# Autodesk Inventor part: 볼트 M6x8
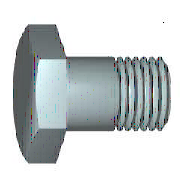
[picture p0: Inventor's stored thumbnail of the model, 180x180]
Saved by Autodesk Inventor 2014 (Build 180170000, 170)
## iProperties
Created: 2012-02
Part Number: 볼트 M6x8
Material: 강철, 연강
Description: 6각 머리 볼트 및 6각 머리 나사
Document SubType Name: Modeling
Standard: KS B 1002
Designer: mduedu
Standards Organization: KS
Language: ko-KR
Size Designation: C  M 6 x 12
Categories: <MemberInstance><Categories><Category DisplayName="조임쇠" InternalName="e4da775c-781d-43d5-af7c-5136215cf5a6" Mnemonic="FSTN"><Category DisplayName="볼트" InternalN
Density: 1 g/cm^3
Appearance: Steel
IsCustomPart: 1
Author: mduedu
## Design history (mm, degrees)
sketch "스케치1"
  geometry: L1 (0, 3)-(8, 3); L2 (8, 3)-(8, 0); L3 (8, 0)-(0, 0); L4 (-2.4, 0)-(14.4, 0) reference; L5 (0, -0.6)-(0, 3.6) reference; L6 (0, 3)-(0, 0)
  constraints: 8 end point, 3 point on line, 1 collinear
  dimensions: "d2" = 6 diameter of L1 L3 (= GD); "d59" = 8 distance between parallel lines of L2 L5 (= NLG)
revolve "본체" sketch "스케치1" stored, may be unused: angle "d12" = 90 deg
sketch "스케치2"
  geometry: L1 (0, 5.774)-(5, 2.887); L2 (5, 2.887)-(5, -2.887); L3 (5, -2.887)-(0, -5.774); L4 (0, -5.774)-(-5, -2.887); L5 (-5, -2.887)-(-5, 2.887); L6 (-5, 2.887)-(0, 5.774); L7 (-7, 0)-(7, 0) reference; L8 (0, 8.083)-(0, -8.083) reference; 2 further points
  constraints: 12 end point, 2 midpoint, 1 coincident, 1 vertical, 11 other
  dimensions: "d11" = 10 distance between parallel lines of L5 L2 (= SW)
extrude "머리" join sketch "스케치2" distance "d3" = 4 (= KOH); taper "d4" = 0 deg
revolve "모따기1" stored, may be unused: angle "d21" = 90 deg
workplane "Work Plane1"
body "Solid1"
feature "스레드" dims "d15" = 9 (= GEL), "d16" = 0
chamfer "모따기2" distance "d6" = 0.61345 (= -0.5 x SPD + 0.5 x GD); stored, may be unused: second distance "d7" = 0.61355 (computed from GUL), angle "d55" = 45 deg
sketch "스케치4"
  geometry: L1 (-3.423, 6)-(-4, 5); L2 (-1.1, 0)-(-0.234, 0); L3 (-4.753, 0)-(0.519, 0) reference; L4 (-4, 6)-(-3.423, 6); L5 (-4, 5)-(-4, 6); L6 (0, 7.2)-(0, -1.2) reference
  constraints: 8 end point, 1 parallel, 1 perpendicular, 1 point on line
  dimensions: "d65" = 10 diameter of L1.end L2 (= SW); "d67" = 30 deg angle of L1 L5 (= ANG1); "d68" = 12 diameter of L4 L2 (= 1.2 x SW); "d69" = 4 distance between parallel lines of L5 L6 (= KOH)
other parameters: "NLG" = 8 [user parameter; used in 1 equation term], "GD" = 6 (= NND) [user parameter; used in 2 equation terms], "BDM" = 6 (= NND) [user parameter], "KOH" = 4 [user parameter; used in 2 equation terms], "GEL" = 9 [user parameter; used in 1 equation term], "SW" = 10 [user parameter; used in 5 equation terms], "SPD" = 4.7731 (= NND - 1.2269 x PTC) [user parameter; used in 1 equation term], "SD2" = 6 (= NND) [user parameter], "SD" = 0 [user parameter], "ANG1" = 30 deg [user parameter; used in 1 equation term], "GAL" = 0.61345 (= 0.61345 x PTC) [user parameter], "GUL" = 0.61345 (= 0.61345 x PTC) [user parameter; used in 1 equation term], "d8" = 0, "RR" = 0.25 [user parameter], "d58" = 0, "RR1" = 0.1 [user parameter], "GD1" = 4.7731 (= THREADDIA - 1.2269 x PTC) [user parameter], "THREADDIA" = 6 [user parameter; used in 1 equation term], "TOA" = 30 deg [user parameter], "PTC" = 1 [user parameter; used in 5 equation terms], "NND" = 6 [user parameter; used in 4 equation terms], "E0" = 11.55 (= 1.155 x SW) [user parameter]
